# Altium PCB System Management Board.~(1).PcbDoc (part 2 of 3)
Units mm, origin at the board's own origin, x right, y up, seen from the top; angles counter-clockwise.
Board outline 150 x 110 mm, 4 copper layers (F.Cu, In1.Cu, In2.Cu, B.Cu); 151 components, 121 nets, 513 pads, 536 vias.
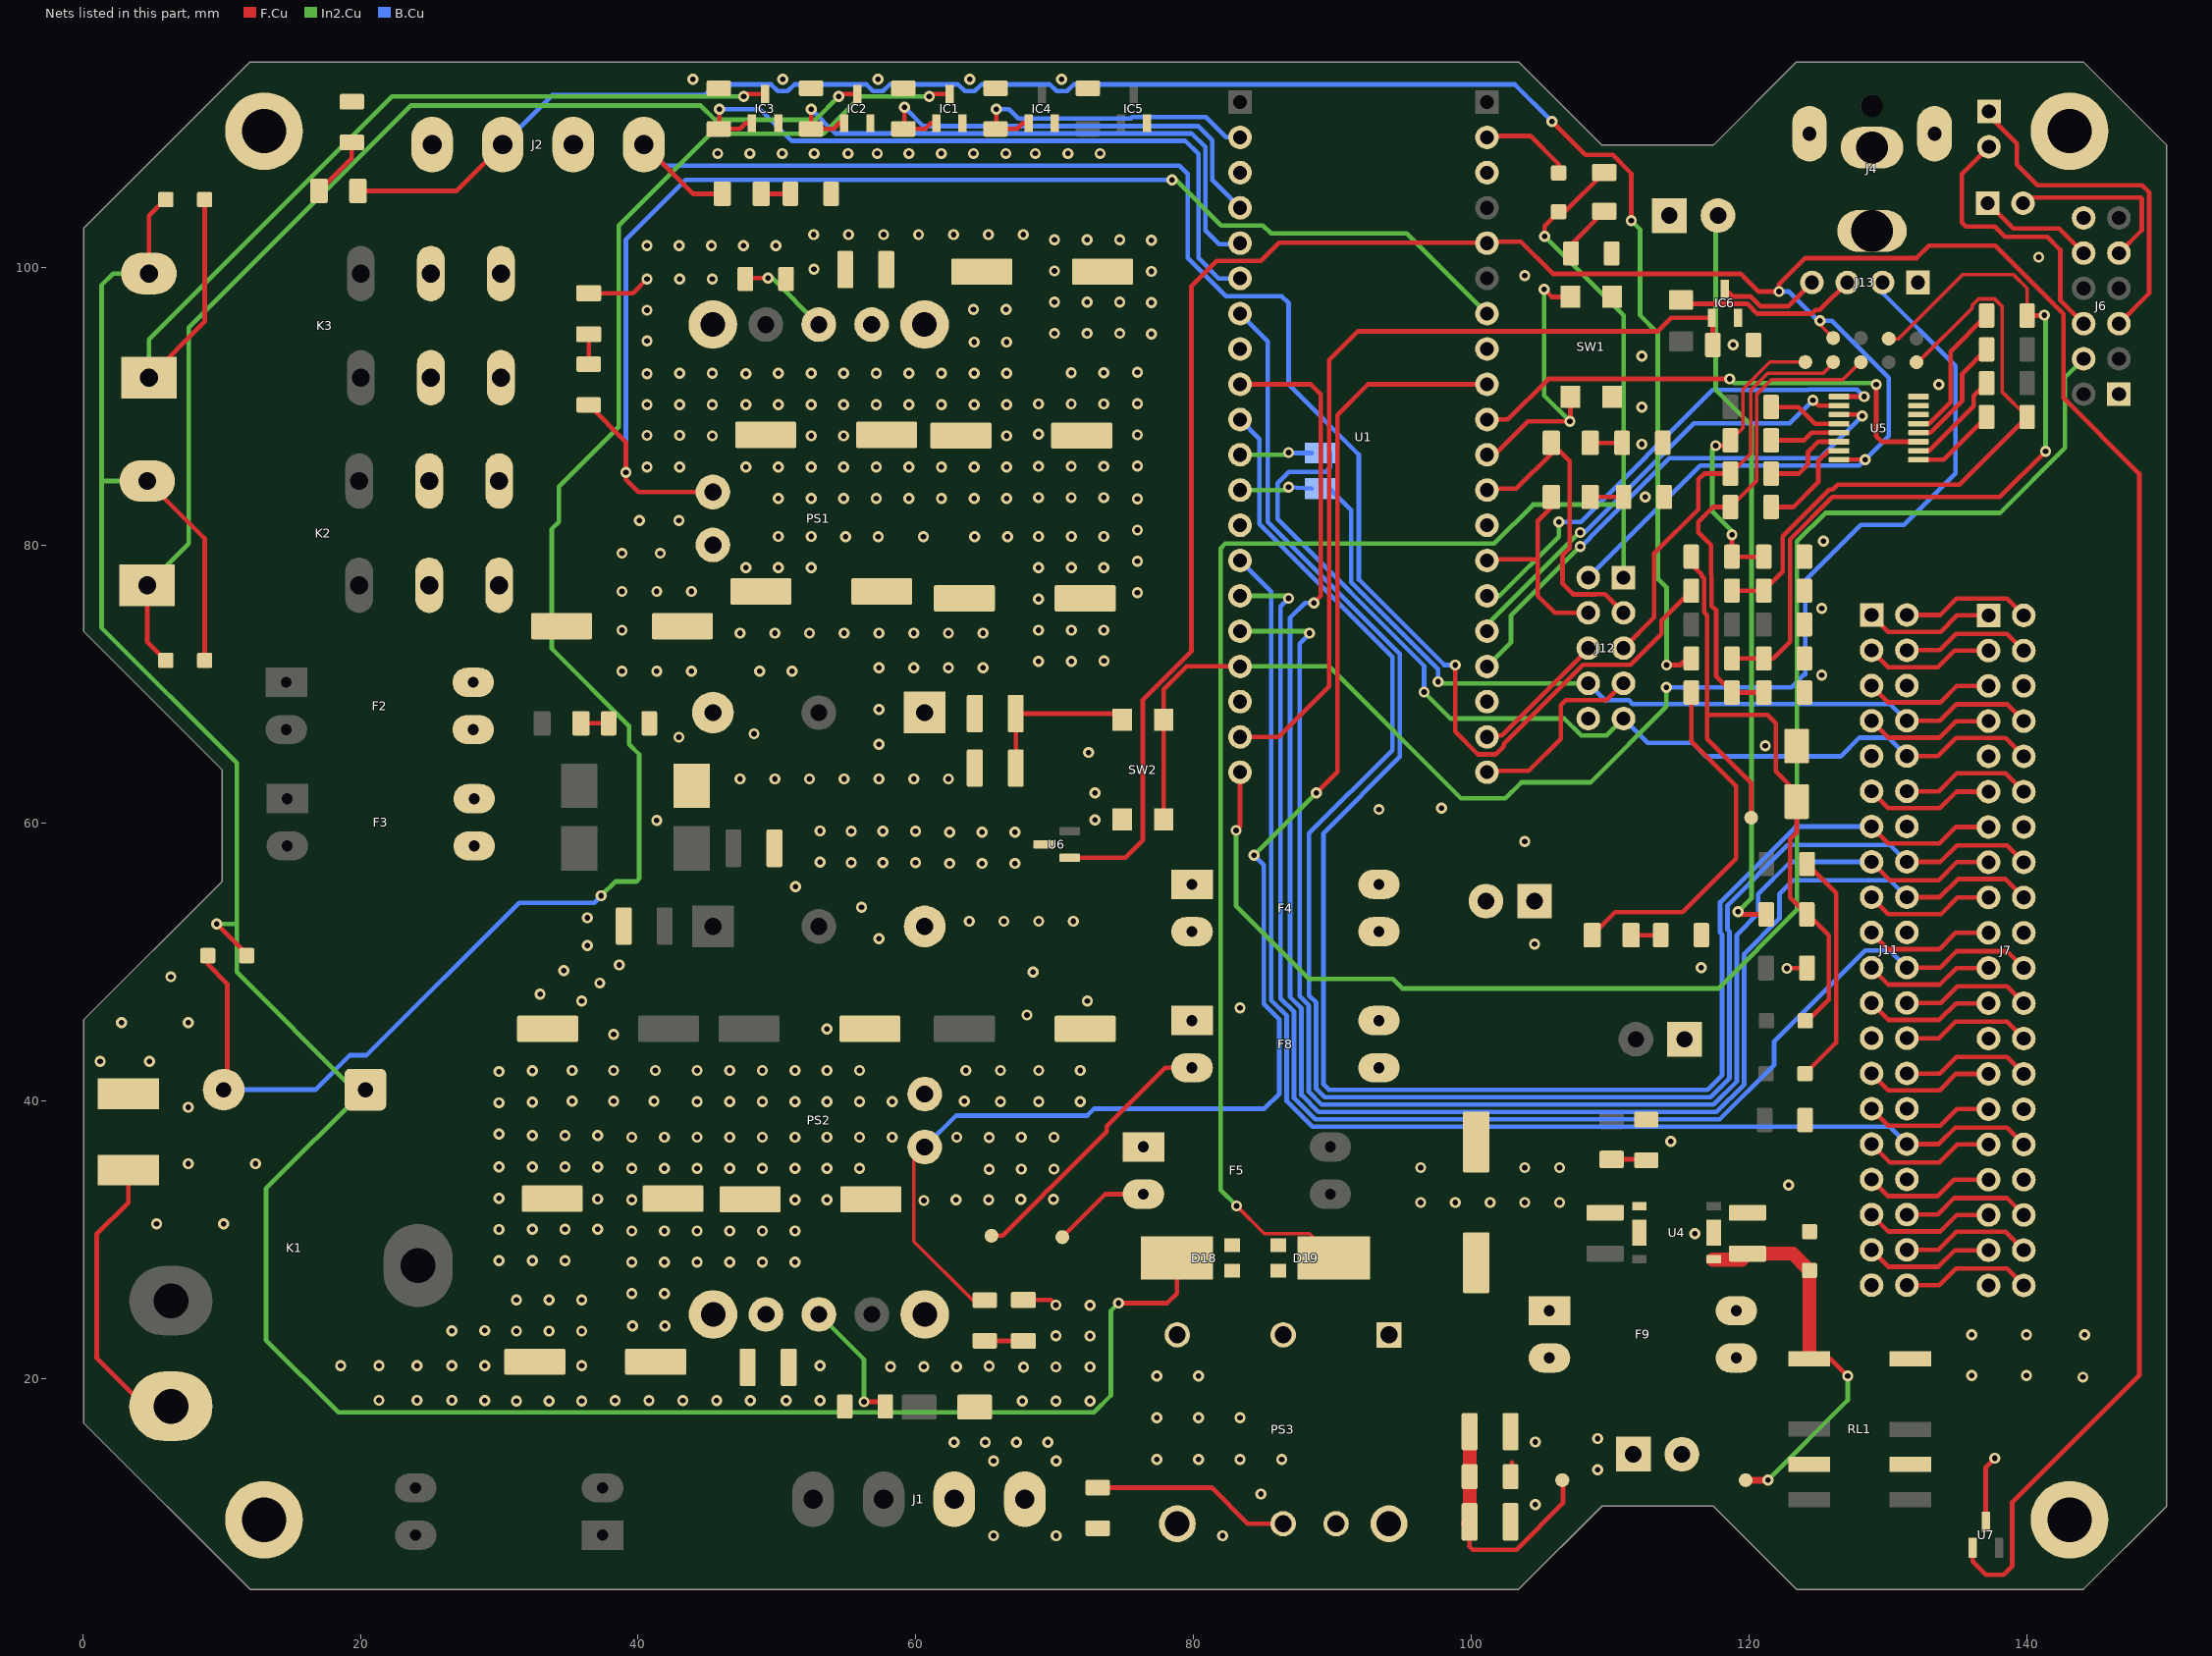
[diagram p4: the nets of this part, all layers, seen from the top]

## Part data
6 7 8 9 10 11 12 13 14 TP1 TP2 TP3 TP4 TP5: library part TestPoint
C1 C2 C3 C4 C9 C10 C11 C12 C15 C16 C22 C25 C26: library part C_Polarized, Voltage=63V
C5 C6 C7 C8 C13 C14 C17 C18 C19 C20 C21 C23 C24 C27: library part C, Voltage=63V
D1 D2: library part D_TVS
D3 D4 D5 D6 D7 D8 D9: library part D
D10 D11 D12 D13 D14 D15 D16 D17: library part LED
D18: library part SBRT15U50SP5-13_1
D19: library part SBRT15U50SP5-13
F1 F2 F3 F4 F5 F8 F9: library part 3557-10
F6 F7 F10: library part Fuse
H1 H2 H3 H4: library part MountingHole_Pad
IC1 IC2 IC3 IC4 IC5 IC6: library part SI2318CDS-T1-GE3, MANUFACTURER_NAME=Vishay
J1 J2: library part Conn_01x04_Male
J3 J8 J9 J10: library part Conn_01x02_Male
J4: library part PJ-063BH, Manufacturer="CUI INC"
J6: library part Conn_02x06_Counter_Clockwise
J7 J11: library part Conn_02x20_Odd_Even
J12: library part Conn_02x05_Top_Bottom
J13: library part Conn_01x04_Female
JP1 JP2: library part Jumper_2_Open
JP3 JP4: library part SolderJumper_2_Bridged
K1: library part RAYEX-L90S
K2 K3: library part J114FL1CS165VDC.41
PS1 PS2: library part I7C4W008A120V-0C3-R, Manufacturer=TDK, MAXIMUM_PACKAGE_HEIGHT="13.5 mm"
PS3: library part I3A4W008A033V-001-R, Manufacturer=TDK-Lambda, MAXIMUM_PACKAGE_HEIGHT=9.6mm
R1 R2 R3 R4 R5 R6 R7 R8 R9 R10 R11 R12 R13 R14 R15 R16 R17 R18 R19 R20 R21 R22 R23 R24 R25 R26 R27 R28 R29 R30 R31 R32 R33 R34 R35 R36 R37 R38 R39 R40 Rup1: library part R
RL1: library part EE2-5NU
SW1: library part SW_Push_4_PIN_1
SW2: library part SW_Push_4_PIN
U1: library part SC0915, Manufacturer="Raspberry Pi", MAXIMUM_PACKAGE_HEIGHT=3.73mm
U4: library part R1560S501B-E2-FE, "test"
U5: library part 74HC4051
U6 U7: library part MCP9700T-ETT

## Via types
v1: diameter 0.8, hole 0.4, F.Cu to B.Cu, tented both sides, 536 vias

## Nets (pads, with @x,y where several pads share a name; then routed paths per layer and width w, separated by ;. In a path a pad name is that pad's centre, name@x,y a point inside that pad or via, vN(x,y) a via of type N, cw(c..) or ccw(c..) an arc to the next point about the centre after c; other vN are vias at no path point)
"5V BOOTSTRAP": C21.1 D3.1 RL1.+ TP2.1 U4.1 | length 30.1
  F.Cu w0.33: D3.1@124.32,27.766 D3.1@124.34,27.787 D3.1@124.34,28.187 ; RL1.+@125.27,21.435 RL1.+@124.32,21.435 125.842,21.435 v1(127.09,20.187)
  F.Cu w0.5: TP2.1@119.74,12.687 v1(121.34,12.687)
  F.Cu w1: U4.1@117.377,28.567 119.448,28.567 C21.1@119.877,28.997 123.13,28.997 D3.1@124.34,27.787 124.34,21.455 RL1.+@124.32,21.435
  In2.Cu w0.33: v1(121.34,12.687) 127.09,18.437 v1(127.09,20.187)
"5V Intermediate": C23.1 C24.1 C27.1 D18.1 D18.2 D19.1 D19.2 PS3.7 PS3.8 TP3.1 | length 18.4
  F.Cu w0.33: C27.1@99.865,9.687 99.865,7.962 99.84,7.937 100.09,7.687 103.254,7.687 106.59,11.022 TP3.1@106.59,12.687 ; 99.94,13.912 99.965,13.937
  F.Cu w1: C27.1@99.727,9.549 C27.1@99.865,9.687 C23.1@99.865,12.937 C24.1@99.865,16.187
"5V Logic PWR": D9.2 D17.2 D19.3 J12.1 | length 125.5
  F.Cu w0.25: v1(83.09,32.437) 85.09,30.437 88.34,30.437 D19.3@90.09,28.687
  F.Cu w0.33: v1(105.258,102.249) 105.258,103.008 D9.2@106.274,104.024 106.722,104.024 D17.2@109.56,106.862
  In2.Cu w0.33: v1(83.09,32.437) 81.94,33.587 81.94,79.787 82.275,80.122 101.623,80.122 104.438,82.937 110.949,82.937 J12.1@110.949,77.686 110.949,96.558 v1(105.258,102.249)
"5V Relay PWR": D4.1 D5.1 D6.1 D18.3 K1.A1 K2.A2 K3.A2 | length 196.6
  F.Cu w0.33: K2.A2@4.655,84.637 8.79,80.501 D5.1@8.79,71.718 ; K3.A2@4.775,99.582 4.775,103.748 D6.1@5.931,104.903 ; v1(9.652,52.745) D4.1@11.814,50.583 ; v1(74.59,25.437) 78.09,25.437 78.786,26.132 D18.3@78.786,28.687
  In2.Cu w0.33: K2.A2@4.655,84.637 1.458,84.637 1.372,84.723 ; K3.A2@4.775,99.582 2.209,99.582 1.372,98.744 1.372,84.723 ; v1(9.652,52.745) 11.1,52.745 ; K1.A1@20.32,40.807 13.208,33.695 13.208,22.773 18.418,17.562 72.813,17.562 74.04,18.79 74.04,24.887 v1(74.59,25.437) ; K1.A1@20.36,41.021 19.344,41.021 11.1,49.265 11.1,52.745 ; 1.372,84.723 1.372,74.055 11.1,64.327 11.1,52.745
"15V Aux PWR OUT PROT": F8.3 F8.4 J9.2
"15v PWR": C9.1 C11.1 C15.1 C17.1 F4.1 F4.2 F8.1 F8.2 PS1.7 PS1.8 TP4.1 | length 19.7
  F.Cu w0.33: TP4.1@65.44,30.287 66.24,30.287 69.136,33.182 69.136,33.217 69.584,33.666 69.619,33.666 73.74,37.787 73.74,38.187 77.936,42.383 F8.2@79.878,42.383
  other v1: 54.79,83.387 57.14,83.387 59.49,83.387 61.84,83.387 64.19,83.387 66.54,83.387 54.79,85.637 57.14,85.637 59.49,85.637 61.84,85.637 64.19,85.637 66.54,85.637 54.79,87.887 66.54,87.887 54.79,90.137 57.14,90.137 59.49,90.137 61.84,90.137 64.19,90.137 66.54,90.137 54.79,92.387 57.14,92.387 59.49,92.387 61.84,92.387 64.19,92.387 66.54,92.387 64.19,94.637 66.54,94.637 64.14,96.987 66.49,96.987 57.675,102.387 60.191,102.387 62.707,102.387 65.224,102.387 67.74,102.387
"48V Aux PWR OUT PROT": F9.3 F9.4 J8.2
"48V PWR": C10.1 C12.1 C16.1 C18.1 F5.1 F5.2 F9.1 F9.2 PS2.7 PS2.8 TP5.1 | length 8.4
  F.Cu w0.33: TP5.1@70.54,30.187 73.636,33.283 F5.2@76.378,33.283 ; F9.1@105.209,25.288 F9.1@105.609,24.888
  F.Cu w1: F5.1@75.878,36.187 F5.1@76.378,36.687
  other v1: 38.34,18.419 40.777,18.419 43.215,18.419 45.652,18.419 48.089,18.419 39.59,23.787 41.94,23.787 39.54,26.137 41.89,26.137 39.54,28.387 41.89,28.387 44.24,28.387 46.59,28.387 48.94,28.387 51.29,28.387 39.54,30.637 41.89,30.637 44.24,30.637 46.59,30.637 48.94,30.637 51.29,30.637 39.54,32.887 51.29,32.887 39.54,35.137 41.89,35.137 44.24,35.137 46.59,35.137 48.94,35.137 51.29,35.137 39.54,37.387 41.89,37.387 44.24,37.387 46.59,37.387 48.94,37.387 51.29,37.387
"Analog Mux OUT": U1.31 U5.3 | length 36.3
  F.Cu w0.33: U1.31@101.12,89.067 102.616,89.067 105.537,91.988 v1(118.59,91.988) ; v1(129.14,91.587) 129.14,87.881 129.554,87.468 U5.3@132.191,87.468
  In2.Cu w0.33: v1(118.59,91.988) 118.891,91.687 129.04,91.687 v1(129.14,91.587)
Aux_ADC_IN: 7.1 J12.5 R14.1 | length 30.3
  F.Cu w0.25: R14.1@118.649,85.167 120.101,86.619 120.101,91.175 121.307,92.38 125.303,92.38 7.1@126.121,93.199
  F.Cu w0.33: J12.5@110.949,72.606 113.157,74.814 113.157,79.415 116.332,82.59 116.332,84.749 116.75,85.167 R14.1@118.649,85.167
Aux_SW: J13.2 SW2.1 U1.17 | length 101.4
  F.Cu w0.33: SW2.1@77.843,60.256 SW2.1@77.843,67.456 77.843,69.628 77.843,69.642 79.487,71.287 U1.17@83.34,71.287
  In2.Cu w0.33: U1.17@83.34,71.287 89.74,71.287 99.24,61.787 102.44,61.787 103.59,62.937 108.59,62.937 114.04,68.387 v1(114.04,69.787)
  B.Cu w0.33: v1(114.04,69.787) 123.04,69.787 123.94,70.687 124.04,70.687 124.04,77.487 128.04,81.487 131.14,81.487 134.84,85.187 134.84,92.937 129.6,98.177 J13.2@129.6,98.937
"Cap Discharge": K1.12 R40.1 | length 19.4
  F.Cu w0.33: R40.1@3.302,35.015 3.302,32.679 1.016,30.393 1.016,21.503 K1.12@4.512,18.007
"COMP PWR CM": PS1.34 R3.2 U1.34 | length 97.7
  F.Cu w0.33: R3.2@36.44,90.124 39.116,87.448 v1(39.116,85.257) 39.116,84.761 40.035,83.842 PS1.34@45.385,83.842
  In2.Cu w0.33: v1(78.44,106.317) 78.71,106.317 81.99,103.037 84.99,103.037 85.565,102.462 95.345,102.462 U1.34@101.12,96.687
  B.Cu w0.33: v1(39.116,85.257) 39.116,102.021 43.412,106.317 v1(78.44,106.317)
"COMP PWR EN": IC4.1 R9.1 U1.2 | length 22.4
  F.Cu w0.33: R9.1@65.736,109.994 67.283,109.994 67.695,110.407 IC4.1@68.107,110.407 ; R9.1@65.786,110.045 v1(65.786,111.419)
  B.Cu w0.33: v1(65.786,111.419) 66.708,111.419 67.39,110.737 75.49,110.737 75.59,110.837 80.89,110.837 82.34,109.387 U1.2@83.34,109.387
"COMP PWR OUT PROT": D13.2 F4.3 F4.4 J4.1 R27.2 | length 26.7
  F.Cu w0.33: D13.2@108.69,51.937 110.34,53.587 115.19,53.587 119.04,57.437 119.04,62.687 115.832,65.895 R27.2@115.832,69.148
  In2.Cu w0.33: J4.1@128.837,101.583 J4.1@128.837,102.644
  other v1: 103.84,58.687
"COMP_Vout MES_ADC": 8.1 R15.1 R27.1 R28.1 | length 35.7
  F.Cu w0.25: R15.1@118.649,82.767 120.551,84.669 120.551,90.892 121.59,91.93 126.734,91.93 8.1@128.028,93.224
  F.Cu w0.33: R15.1@118.649,82.767 117.398,82.767 116.332,81.701 116.332,80.939 117.243,80.028 117.243,77.888 117.289,77.842 117.289,75.651 117.624,75.316 117.624,70.543 R27.1@118.756,69.411 R28.1@121.044,69.411
CPS_IN_PROT: C1.1 C2.1 C3.1 C5.1 C7.1 F6.2 PS1.1
  other v1: 47.34,63.187 49.84,63.187 52.34,63.187 54.84,63.187 57.34,63.187 59.84,63.187 62.34,63.187 57.34,65.687 57.34,68.187 57.34,71.187 59.84,71.187 62.34,71.187 64.84,71.187 47.34,73.687 49.84,73.687 52.34,73.687 54.84,73.687 57.34,73.687 59.84,73.687 62.34,73.687 64.84,73.687
Ext_Relay_LOW_SIDE: IC6.3 J13.4 | length 7.5
  F.Cu w0.33: IC6.3@118.252,98.488 118.807,97.933 120.087,97.933 120.803,97.217 122.8,97.217 J13.4@124.52,98.937
Ext_Relay_Trig: IC6.1 R39.1 U1.19 | length 62.2
  F.Cu w0.33: U1.19@83.34,66.207 86.106,66.207 89.74,69.841 89.74,93.336 91.826,95.422 113.416,95.422 114.382,96.388 IC6.1@117.302,96.388 117.377,96.312 R39.1@117.378,94.437
GND: C1.2 C2.2 C3.2 C4.2 C5.2 C6.2 C7.2 C8.2 C9.2 C10.2 C11.2 C12.2 C13.2 C14.2 C15.2 C16.2 C17.2 C18.2 C19.2 C20.2 C21.2 C22.2 C23.2 C24.2 C25.2 C26.2 C27.2 D1.1 D2.1 D3.2 H1.1 H2.1 H3.1 H4.1 IC1.2 IC2.2 IC3.2 IC4.2 IC5.2 IC6.2 J1.1 J1.2 J2.2 J2.4 J3.1 J4.2 J4.S1 J4.S2 J6.1 J6.12 J7.6 J7.9 J7.14 J7.20 J7.25 J7.30 J7.34 J7.39 J8.1 J9.1 J10.1 J11.6 J11.9 J11.14 J11.20 J11.25 J11.30 J11.34 J11.39 J12.10 J13.1 PS1.3 PS1.4 PS1.32 PS2.3 PS2.4 PS2.32 PS3.2 PS3.3 PS3.4 R1.2 R2.2 R6.2 R7.2 R8.2 R9.2 R10.2 R12.1 R22.2 R24.2 R26.2 R28.2 R30.2 R31.2 R32.2 R33.2 R34.2 R35.2 R36.1 R37.1 R38.1 R39.2 R40.2 RL1.- Rup1.1 SW1.1 SW2.2 U1.3 U1.8 U1.13 U1.18 U1.23 U1.28 U1.33 U1.38 U4.2 U4.4 U4.5 U5.6 U5.7 U5.8 U6.3 U7.3 | length 25.3
  F.Cu w0.25: C14.2@67.727,25.649 C14.2@67.74,25.662
  F.Cu w0.33: C13.2@36.44,98.162 39.63,98.162 v1(40.64,99.172) ; C5.2@67.19,63.962 C7.2@67.19,67.887 74.412,67.887 SW2.2@74.843,67.456 ; C14.2@67.74,25.662 69.708,25.662 v1(70.079,25.291) ; C27.2@102.815,10.437 C27.2@102.915,10.537 ; 102.915,13.937 102.922,13.944 ; v1(122.707,49.544) 122.733,49.57 C19.2@124.157,49.57 ; U7.3@137.029,9.69 137.029,13.625 v1(137.668,14.264)
  other v1: 65.59,8.687 70.09,8.687 82.09,8.687 104.59,10.937 84.84,11.687 109.09,13.437 65.59,14.082 70.09,14.082 77.34,14.187 80.34,14.187 83.34,14.187 86.34,14.187 62.738,15.407 64.988,15.407 67.238,15.407 69.488,15.407 104.59,15.437 109.09,15.687 77.34,17.187 80.34,17.187 83.34,17.187 72.542,18.374 31.24,18.387 33.59,18.387 35.94,18.387 67.667,18.378 70.079,18.378 28.955,18.423 50.654,18.419 53.091,18.419 21.34,18.437 24.09,18.437 26.59,18.437 144.018,20.106 77.34,20.187 80.34,20.187 136.017,20.233 139.954,20.233 67.755,20.827 70.079,20.846 72.542,20.842 58.166,20.868 60.579,20.868 62.929,20.868 65.278,20.887 18.59,20.937 21.34,20.937 24.09,20.937 26.59,20.937 28.956,20.937 35.941,20.937 53.09,20.937 72.543,23.073 70.08,23.077 136.017,23.154 139.954,23.154 144.145,23.154 31.241,23.427 33.591,23.427 35.941,23.427 26.59,23.437 28.956,23.463 72.542,25.287 31.241,25.677 33.591,25.677 35.941,25.677 29.972,28.488 32.385,28.505 34.735,28.505 116.09,30.437 29.972,30.738 32.385,30.755 34.735,30.755 37.085,30.755 5.334,31.155 10.16,31.155 96.34,32.687 98.84,32.687 101.34,32.687 103.84,32.687 106.34,32.687 60.579,32.823 53.594,32.878 62.89,32.887 65.24,32.887 67.551,32.901 69.901,32.901 37.084,32.933 29.972,32.988 122.84,33.937 65.279,35.073 67.59,35.087 69.94,35.087 53.594,35.128 55.944,35.128 96.34,35.187 103.84,35.187 106.34,35.187 29.972,35.238 32.385,35.255 34.735,35.255 37.085,35.255 7.62,35.473 12.446,35.473 114.34,37.087 65.279,37.373 53.594,37.378 55.944,37.378 58.294,37.378 62.94,37.387 67.59,37.387 69.94,37.387 32.385,37.505 34.735,37.505 37.085,37.505 29.972,37.613 7.62,39.537 29.972,39.863 32.384,39.918 44.24,39.937 46.59,39.937 48.94,39.937 51.29,39.937 53.593,39.935 55.943,39.935 58.293,39.935 66.09,39.937 68.84,39.937 71.84,39.937 35.24,39.987 38.24,39.987 41.14,39.987 63.49,39.987 29.972,42.113 32.384,42.168 35.24,42.187 38.24,42.187 41.24,42.187 44.24,42.187 46.59,42.187 48.94,42.187 51.29,42.187 53.593,42.185 55.943,42.185 63.59,42.185 66.09,42.185 68.84,42.187 71.84,42.187 1.27,42.839 4.826,42.839 38.24,44.787 53.59,45.187 2.794,45.633 7.62,45.633 67.991,46.185 83.34,46.687 35.94,47.187 72.34,47.187 32.94,47.687 37.24,48.487 6.35,48.935 68.44,49.287 34.64,49.387 116.54,49.587 38.64,49.787 36.34,51.187 104.54,51.287 57.34,51.687 63.84,52.937 66.34,52.937 68.84,52.937 71.34,52.937 36.34,53.187 56.09,53.937 51.34,55.437 62.42,57.099 64.77,57.099 67.12,57.099 53.09,57.187 55.34,57.164 57.62,57.164 59.97,57.164 62.42,59.349 64.77,59.349 67.12,59.349 55.34,59.414 57.62,59.414 59.97,59.414 53.09,59.437 41.34,60.187 72.898,60.238 93.34,60.987 97.84,61.087 72.898,62.187 72.44,65.087 121.158,65.572 42.94,66.187 48.34,66.437 125.222,70.652 38.84,70.937 41.34,70.937 43.84,70.937 48.74,70.937 51.09,70.937 68.834,71.649 71.184,71.649 73.54,71.687 38.84,73.899 68.834,73.899 71.184,73.899 73.534,73.899 125.222,75.478 68.834,76.149 75.946,76.602 38.84,76.687 41.34,76.687 43.84,76.687 47.751,78.399 50.101,78.399 52.451,78.399 68.834,78.399 71.184,78.399 73.534,78.399 75.946,78.852 38.84,79.437 41.59,79.437 125.349,80.304 50.101,80.649 52.451,80.649 54.94,80.637 57.29,80.637 60.54,80.637 64.24,80.637 66.59,80.637 68.834,80.649 71.184,80.649 73.534,80.649 75.946,81.102 40.09,81.787 42.94,81.787 75.946,83.352 50.101,83.388 52.451,83.388 68.833,83.443 71.183,83.443 73.533,83.443 112.522,83.479 40.639,85.638 42.989,85.638 47.751,85.638 50.101,85.638 52.451,85.638 68.833,85.693 71.183,85.693 73.533,85.693 75.946,85.71 112.268,87.289 45.339,87.888 52.451,87.888 40.64,87.924 42.99,87.924 75.946,87.96 68.834,88.015 112.268,89.956 40.639,90.138 42.989,90.138 45.339,90.138 47.751,90.138 50.101,90.138 52.451,90.138 68.833,90.193 71.183,90.193 73.533,90.193 75.946,90.21 133.64,91.587 40.64,92.369 42.989,92.388 45.339,92.388 47.752,92.369 50.101,92.388 52.451,92.388 71.183,92.443 73.533,92.443 75.946,92.46 112.268,93.639 118.84,94.437 40.64,94.727 76.962,95.235 69.977,95.271 72.327,95.271 74.677,95.271 40.639,96.941 76.962,97.485 69.977,97.521 72.327,97.521 74.677,97.521 42.989,99.191 45.339,99.191 103.84,99.437 76.962,99.735 69.977,99.771 52.654,99.887 140.843,100.751 40.64,101.585 42.958,101.585 45.276,101.585 47.593,101.585 49.911,101.585 76.962,101.985 69.977,102.021 72.327,102.021 74.677,102.021 52.642,102.387 55.158,102.387 45.733,108.219 48.05,108.219 50.368,108.219 52.683,108.219 55.105,108.219 57.213,108.219 59.497,108.219 61.822,108.219 64.149,108.219 66.478,108.219 68.602,108.219 70.948,108.219 73.264,108.219 43.942,113.578 50.419,113.578 57.277,113.578 63.881,113.578 70.485,113.578
i3_Vin: C22.1 PS3.1 RL1.C1 RL1.C2 | length 1
  F.Cu w0.33: RL1.C1@124.32,13.815 RL1.C1@124.324,13.81
  F.Cu w1: RL1.C1@123.37,13.815 RL1.C1@124.32,13.815 ; RL1.C2@131.592,13.815 RL1.C2@131.597,13.81
JET_ON: J6.4 U1.20 | length 110.5
  F.Cu w0.33: v1(83.058,59.476) 83.34,59.758 U1.20@83.34,63.667
  In2.Cu w0.33: v1(83.058,59.476) 83.058,54.015 88.286,48.787 94.34,48.787 95.04,48.087 117.77,48.087 123.444,53.761 123.444,80.304 125.476,82.336 138.049,82.336 142.74,87.027 142.74,92.095 J6.4@144.076,93.431
JET_P1: J7.1 J11.1 | length 9.4
  F.Cu w0.33: J11.1@128.808,74.991 130.023,73.775 133.779,73.775 134.968,74.965 J7.1@137.227,74.965
JET_P2: J7.2 J11.2 | length 9.4
  F.Cu w0.33: J11.2@131.348,74.991 133.744,74.991 134.933,76.18 138.552,76.18 J7.2@139.767,74.965
JET_P3: J7.3 J11.3 | length 9.4
  F.Cu w0.33: J11.3@128.808,72.451 130.023,71.235 133.589,71.235 134.778,72.425 J7.3@137.227,72.425
JET_P4: J7.4 J11.4 | length 9.4
  F.Cu w0.33: J11.4@131.348,72.451 133.704,72.451 134.893,73.64 138.552,73.64 J7.4@139.767,72.425
JET_P5: J7.5 J11.5 | length 9.4
  F.Cu w0.33: J11.5@128.808,69.911 130.023,68.695 133.749,68.695 134.938,69.885 J7.5@137.227,69.885
JET_P7: J7.7 J11.7 | length 9.4
  F.Cu w0.33: J11.7@128.808,67.371 130.023,66.155 133.709,66.155 134.898,67.345 J7.7@137.227,67.345
JET_P11: J7.11 J11.11 | length 9.4
  F.Cu w0.33: J11.11@128.808,62.291 130.023,61.075 133.729,61.075 134.918,62.265 J7.11@137.227,62.265
JET_P12: J7.12 J11.12 | length 9.5
  F.Cu w0.33: J11.12@131.348,62.291 133.644,62.291 134.94,63.587 138.445,63.587 J7.12@139.767,62.265
JET_P17: J7.17 J11.17 | length 9.4
  F.Cu w0.33: J11.17@128.808,54.671 130.023,53.455 133.809,53.455 134.998,54.645 J7.17@137.227,54.645
JET_P19: J7.19 J11.19 | length 9.4
  F.Cu w0.33: J11.19@128.808,52.131 130.023,50.915 133.669,50.915 134.858,52.105 J7.19@137.227,52.105
JET_P21: J7.21 J11.21 | length 9.4
  F.Cu w0.33: J11.21@128.808,49.591 130.023,48.375 133.729,48.375 134.918,49.565 J7.21@137.227,49.565
JET_P23: J7.23 J11.23 | length 9.4
  F.Cu w0.33: J11.23@128.808,47.051 130.023,45.835 133.689,45.835 134.878,47.025 J7.23@137.227,47.025
JET_P24: J7.24 J11.24 | length 9.4
  F.Cu w0.33: J11.24@131.348,47.051 133.804,47.051 134.993,48.24 138.552,48.24 J7.24@139.767,47.025
JET_P26: J7.26 J11.26 | length 9.4
  F.Cu w0.33: J11.26@131.348,44.511 133.664,44.511 134.853,45.7 138.552,45.7 J7.26@139.767,44.485
JET_P27: J7.27 J11.27 | length 9.4
  F.Cu w0.33: J11.27@128.808,41.971 130.023,40.755 133.709,40.755 134.898,41.945 J7.27@137.227,41.945
JET_P28: J7.28 J11.28 | length 9.4
  F.Cu w0.33: J11.28@131.348,41.971 133.724,41.971 134.913,43.16 138.552,43.16 J7.28@139.767,41.945
JET_P29: J7.29 J11.29 | length 9.4
  F.Cu w0.33: J11.29@128.808,39.431 130.023,38.215 133.769,38.215 134.958,39.405 J7.29@137.227,39.405
JET_P31: J7.31 J11.31 | length 9.5
  F.Cu w0.33: J11.31@128.808,36.891 130.133,35.566 133.697,35.566 134.996,36.865 J7.31@137.227,36.865
JET_P33: J7.33 J11.33 | length 9.4
  F.Cu w0.33: J11.33@128.808,34.351 130.023,33.135 133.551,33.135 134.74,34.325 J7.33@137.227,34.325
JET_P35: J7.35 J11.35 | length 9.4
  F.Cu w0.33: J11.35@128.808,31.811 130.023,30.595 133.749,30.595 134.938,31.785 J7.35@137.227,31.785
JET_P36: J7.36 J11.36 | length 9.4
  F.Cu w0.33: J11.36@131.348,31.811 133.564,31.811 134.753,33 138.552,33 J7.36@139.767,31.785
JET_P37: J7.37 J11.37 | length 9.4
  F.Cu w0.33: J11.37@128.808,29.271 130.023,28.055 133.609,28.055 134.798,29.245 J7.37@137.227,29.245
JET_P38: J7.38 J11.38 | length 9.5
  F.Cu w0.33: J11.38@131.348,29.271 133.624,29.271 134.923,30.57 138.442,30.57 J7.38@139.767,29.245
JET_P40: J7.40 J11.40 | length 9.4
  F.Cu w0.33: J11.40@131.348,26.731 133.684,26.731 134.873,27.92 138.552,27.92 J7.40@139.767,26.705
Jet_UART1_Rx: J7.10 J11.10 J12.9 JP3.1 | length 73
  F.Cu w0.33: J11.10@131.348,64.831 133.584,64.831 134.883,66.13 138.442,66.13 J7.10@139.767,64.805
  In2.Cu w0.33: v1(96.59,69.437) 98.495,67.531 106.685,67.531 107.906,66.31 109.734,66.31 J12.9@110.949,67.526
  B.Cu w0.33: JP3.1@89.8,86.654 89.8,85.573 89.513,85.287 86.858,85.287 86.04,84.469 86.04,81.887 96.59,71.337 v1(96.59,69.437) ; J12.9@110.949,67.526 112.688,65.787 115.924,65.787 116.904,64.806 126.591,64.806 127.94,66.155 130.023,66.155 J11.10@131.348,64.831
Jet_UART1_Tx: J7.8 J11.8 J12.8 JP4.1 | length 61.5
  F.Cu w0.33: J11.8@131.348,67.371 133.724,67.371 134.913,68.56 138.552,68.56 J7.8@139.767,67.345
  In2.Cu w0.33: v1(97.59,70.187) 97.711,70.066 J12.8@108.409,70.066
  B.Cu w0.33: JP4.1@89.8,84.09 91.34,82.55 91.34,77.336 97.59,71.086 v1(97.59,70.187) ; J12.8@108.409,70.066 109.624,68.85 111.343,68.85 111.607,68.586 130.133,68.586 J11.8@131.348,67.371
"KeySW_Vin MES_ADC": 6.1 R13.1 R21.1 R22.1 | length 21.6
  F.Cu w0.25: R13.1@118.649,87.567 119.536,88.454 119.536,91.246 121.495,93.205 6.1@124.04,93.205
  F.Cu w0.33: v1(117.59,87.187) 118.269,87.187 R13.1@118.649,87.567 ; v1(118.757,80.77) R21.1@118.756,79.187 R22.1@121.044,79.187
  In2.Cu w0.33: v1(117.59,87.187) 117.34,86.937 117.34,82.437 118.757,81.02 v1(118.757,80.77)
"KeySwitch IN": D2.2 D7.2 R5.2 R21.2 TP1.1 | length 50.2
  F.Cu w0.33: R21.2@115.832,79.187 115.832,78.645 116.586,77.891 116.586,77.795 116.759,77.623 116.759,75.178 116.967,74.97 116.967,68.239 ; TP1.1@120.14,60.387 120.14,62.887 116.967,66.06 116.967,68.239 ; R5.2@124.144,53.43 122.936,54.639 122.936,58.841 123.416,59.321 D2.2@123.416,61.554 123.416,62.232 121.923,63.724 121.923,67.185 121.322,67.787 116.967,67.787 116.967,68.239 ; D7.2@124.216,45.77 125.73,47.284 125.73,51.932 R5.2@124.231,53.43
"Light A Relay EN": IC2.1 R7.1 U1.5 | length 42.4
  F.Cu w0.33: R7.1@52.45,109.994 54.075,109.994 54.487,110.407 IC2.1@54.822,110.407 ; R7.1@52.45,109.994 v1(52.451,111.419)
  B.Cu w0.33: v1(52.451,111.419) 54.207,109.662 78.083,109.662 79.864,109.662 80.84,108.687 80.84,102.687 81.84,101.687 82.68,101.687 82.76,101.767 U1.5@83.34,101.767
"Light B Relay EN": IC3.1 R8.1 U1.6 | length 50.9
  F.Cu w0.33: R8.1@45.808,109.994 47.344,109.994 47.756,110.407 IC3.1@48.179,110.407 ; R8.1@45.847,110.034 v1(45.847,111.419)
  B.Cu w0.33: v1(45.847,111.419) 48.768,111.419 51.054,109.133 79.394,109.133 80.34,108.187 80.34,100.687 81.8,99.227 U1.6@83.34,99.227
"LIGHT BANK A PROT": F2.3 F2.4 K2.11
"LIGHT BANK A PROT SW": D11.2 J2.1 K2.14 R25.2 | length 121.3
  F.Cu w0.33: J2.1@40.41,108.862 43.951,105.321 D11.2@46.06,105.321 ; v1(98.84,71.387) 98.84,66.587 100.479,64.947 101.74,64.947 102.335,65.542 102.335,65.71 108.015,71.39 111.452,71.39 113.687,73.625 113.687,74.598 R25.2@115.832,76.743
  B.Cu w0.33: J2.1@40.41,108.862 41.917,107.355 78.972,107.355 79.575,106.752 79.575,100.702 82.326,97.95 86.335,97.95 86.84,97.445 86.84,91.594 91.89,86.544 91.89,77.536 98.04,71.387 v1(98.84,71.387)
"LIGHT BANK B PROT": F3.3 F3.4 K3.11
"LIGHT BANK B PROT SW": D12.2 J2.3 K3.14 R29.2 | length 137.2
  F.Cu w0.33: D12.2@19.827,105.522 26.91,105.522 J2.3@30.25,108.862 ; v1(105.791,110.53) 108.204,108.117 110.182,108.117 111.506,106.792 v1(111.506,103.387) ; v1(114.046,71.387) 115.035,71.387 R29.2@115.503,71.855
  In2.Cu w0.33: v1(111.506,103.387) 112.141,102.752 112.141,96.56 113.411,95.29 113.411,77.631 114.046,76.996 v1(114.046,71.387)
  B.Cu w0.33: J2.3@30.25,108.862 33.823,112.435 44.831,112.435 45.593,113.197 49.577,113.197 50.061,112.713 50.777,112.713 51.261,113.197 56.435,113.197 56.919,112.713 57.635,112.713 58.119,113.197 63.039,113.197 63.523,112.713 64.239,112.713 64.723,113.197 69.643,113.197 70.127,112.713 70.89,112.713 71.374,113.197 103.124,113.197 v1(105.791,110.53)
"Light_A_Vout MES_ADC": 10.1 R17.1 R25.1 R26.1 | length 45
  F.Cu w0.25: 10.1@132.04,93.187 132.143,93.187 136.04,97.083 136.04,97.287 136.505,97.752 137.659,97.752 138.224,97.187 138.224,91.039 R17.1@140.011,89.252
  F.Cu w0.33: R25.1@118.756,76.743 R26.1@121.044,76.743 122.406,78.105 122.406,80.65 125.765,84.008 126.019,84.008 126.378,84.368 135.127,84.368 R17.1@140.011,89.252
"Light_B_Vout MES_ADC": 12.1 R18.1 R29.1 R30.1 | length 58.4
  F.Cu w0.25: 12.1@130.04,94.887 130.74,94.887 135.34,99.487 139.04,99.487 140.012,98.515 R18.1@140.011,96.552
  F.Cu w0.33: R29.1@118.756,71.855 R30.1@121.044,71.855 121.726,71.855 122.936,73.065 122.936,80.431 125.984,83.479 138.032,83.479 v1(141.34,86.787) ; R18.1@140.011,96.552 141.205,96.552 v1(141.24,96.587)
  In2.Cu w0.33: v1(141.24,96.587) 141.34,96.487 v1(141.34,86.787)
"Main Relay EN": IC1.1 R6.1 U1.4 | length 32.8
  F.Cu w0.33: R6.1@59.093,109.994 60.679,109.994 61.091,110.407 IC1.1@61.464,110.407 ; R6.1@59.182,110.084 v1(59.182,111.546)
  B.Cu w0.33: v1(59.182,111.546) 60.536,110.192 78.303,110.192 78.308,110.187 80.34,110.187 81.34,109.187 81.34,106.307 U1.4@83.34,104.307
MUX_S0: U1.24 U5.11 | length 37.4
  F.Cu w0.33: U5.11@126.466,89.418 128.046,89.418 v1(128.143,89.321)
  In2.Cu w0.33: U1.24@101.12,71.287 102.84,73.007 102.84,74.936 v1(107.826,79.922)
  B.Cu w0.33: v1(107.826,79.922) 107.908,79.922 108.591,80.605 108.591,80.63 114.248,86.287 125.109,86.287 v1(128.143,89.321)
MUX_S1: U1.25 U5.10 | length 32.7
  F.Cu w0.33: v1(124.587,90.464) 124.983,90.068 U5.10@126.466,90.068
  In2.Cu w0.33: U1.25@101.12,73.827 101.12,74.298 107.744,80.922 v1(107.826,80.922)
  B.Cu w0.33: v1(107.826,80.922) 108.134,80.922 115.998,88.787 122.91,88.787 v1(124.587,90.464)
MUX_S2: U1.26 U5.9 | length 35.9
  F.Cu w0.33: U5.9@126.466,90.718 v1(128.27,90.718)
  In2.Cu w0.33: U1.26@101.12,76.367 102.02,76.367 106.296,80.642 v1(106.296,81.687)
  B.Cu w0.33: v1(106.296,81.687) 107.87,81.687 117.37,91.187 124.228,91.187 124.27,91.229 127.759,91.229 v1(128.27,90.718)
NetC13_1: C13.1 R3.1 | length 2.2
  F.Cu w0.33: R3.1@36.44,93.049 C13.1@36.44,95.212
NetC14_1: C14.1 R4.1 | length 2.8
  F.Cu w0.33: R4.1@64.96,22.724 64.972,22.712 C14.1@67.74,22.712
NetD4_2: D4.2 IC1.3 K1.A2 | length 125.6
  F.Cu w0.33: D4.2@9.014,50.459 9.014,49.827 10.414,48.427 K1.A2@10.414,41.061 ; v1(60.96,112.332) 61.135,112.507 IC1.3@62.414,112.507
  In2.Cu w0.33: v1(37.338,54.777) 38.354,55.793 39.878,55.793 40.075,55.989 40.075,64.952 39.34,65.687 39.34,66.999 33.782,72.557 33.782,81.193 34.29,81.701 34.29,84.241 38.608,88.559 38.608,103.037 45.212,109.641 53.34,109.641 56.031,112.332 v1(60.96,112.332)
  B.Cu w0.33: K1.A2@10.16,40.807 16.76,40.807 19.24,43.287 20.44,43.287 31.422,54.269 36.83,54.269 v1(37.338,54.777)
NetD5_2: D5.2 IC2.3 K2.A1 | length 81.7
  F.Cu w0.33: K2.A1@4.655,77.137 4.655,73.054 D5.2@5.99,71.718 ; v1(54.451,112.332) 54.626,112.507 IC2.3@55.772,112.507
  In2.Cu w0.33: K2.A1@4.655,77.137 7.645,80.127 7.645,95.696 23.622,111.673 44.511,111.673 45.53,110.653 52.773,110.653 v1(54.451,112.332)
NetD6_2: D6.2 IC3.3 K3.A1 | length 68.9
  F.Cu w0.33: K3.A1@4.775,92.082 8.79,96.097 D6.2@8.79,104.903 ; v1(47.598,112.332) 47.773,112.507 IC3.3@49.129,112.507
  In2.Cu w0.33: K3.A1@4.775,92.082 4.775,94.832 22.275,112.332 v1(47.598,112.332)
NetD8_2: D8.2 R11.2 | length 16.9
  F.Cu w0.33: D8.2@124.017,41.96 126.26,44.203 126.26,54.957 R11.2@124.166,57.051
NetD9_1: D9.1 U1.39 | length 6
  F.Cu w0.33: U1.39@101.76,109.492 104.238,109.492 106.274,107.456 D9.1@106.274,106.824
NetD10_1: D10.1 R31.1 | length 2.3
  F.Cu w0.33: D10.1@35.884,67.411 D10.1@35.884,67.187 ; D10.1@35.95,67.253 D10.1@35.884,67.187 ; R31.1@37.878,67.187 D10.1@35.884,67.187
NetD11_1: D11.1 R32.1 | length 2.1
  F.Cu w0.33: D11.1@48.86,105.321 R32.1@50.969,105.321
NetD12_1: D12.1 R33.1 | length 4.5
  F.Cu w0.33: D12.1@17.027,105.522 19.391,107.886 R33.1@19.391,109.022
NetD13_1: D13.1 R34.1 | length 2.1
  F.Cu w0.33: D13.1@111.49,51.937 R34.1@113.628,51.937
NetD14_1: D14.1 R35.1 | length 2.5
  F.Cu w0.33: D14.1@110.09,35.787 112.527,35.787 R35.1@112.59,35.724
NetD15_1: D15.1 R36.2 | length 2.3
  F.Cu w0.33: D15.1@108.55,87.388 R36.2@110.847,87.388
NetD16_1: D16.1 R37.2 | length 2.4
  F.Cu w0.33: D16.1@108.55,83.488 R37.2@110.956,83.488
NetD17_1: D17.1 R38.2 | length 3.4
  F.Cu w0.33: R38.2@107.167,101.669 D17.1@109.56,104.062
NetF10_2: F10.2 J13.3 | length 13.3
  F.Cu w0.33: F10.2@115.09,97.674 115.361,97.403 119.867,97.403 120.583,96.687 124.508,96.687 124.773,96.952 125.075,96.952 J13.3@127.06,98.937
NetJ6_5: J6.5 JP1.1 | length 25.1
  F.Cu w0.33: JP1.1@137.259,110.939 139.268,108.929 139.268,107.431 140.767,105.932 148.285,105.932 148.793,105.424 148.793,98.148 J6.5@146.616,95.971
NetJ6_6: J6.6 JP1.2 | length 20.2
  F.Cu w0.33: JP1.2@137.259,108.704 135.306,106.751 135.306,103.24 135.585,102.96 137.693,102.96 138.421,102.233 139.056,102.233 139.065,102.224 141.453,102.224 142.392,101.284 142.392,97.652 142.494,97.55 142.496,97.55 J6.6@144.076,95.971
NetJ6_9: J6.9 JP2.2 | length 12.8
  F.Cu w0.33: JP2.2@140.112,105.043 148.209,105.043 148.263,104.989 148.263,102.698 J6.9@146.616,101.051
NetJ6_10: J6.10 JP2.1 | length 8.4
  F.Cu w0.33: JP2.1@137.208,104.64 139.014,102.833 142.293,102.833 J6.10@144.076,101.051
NetJ10_2: J10.2 R5.1 | length 53.8
  F.Cu w0.33: v1(119.202,53.634) 119.405,53.43 R5.1@121.22,53.43
  In2.Cu w0.33: J10.2@117.748,103.751 117.59,103.593 117.59,91.187 120.167,88.609 120.167,54.599 v1(119.202,53.634)
NetJP3_2: JP3.2 U1.11 | length 5.2
  In2.Cu w0.33: U1.11@83.34,86.527 86.68,86.527 v1(86.84,86.687)
  B.Cu w0.33: v1(86.84,86.687) 86.873,86.654 JP3.2@88.5,86.654
NetJP4_2: JP4.2 U1.12 | length 5.2
  In2.Cu w0.33: U1.12@83.34,83.987 86.64,83.987 v1(86.84,84.187)
  B.Cu w0.33: v1(86.84,84.187) JP4.2@88.5,84.09
NetPS1_6: PS1.6 R1.1 | length 6.6
  F.Cu w0.33: R1.1@47.793,99.252 v1(49.352,99.252)
  In2.Cu w0.33: v1(49.352,99.252) 49.655,99.252 PS1.6@53.005,95.902
NetPS2_6: PS2.6 R2.1 | length 8.8
  F.Cu w0.33: v1(56.261,18.328) R2.1@57.466,18.328
  In2.Cu w0.33: PS2.6@53.015,24.622 56.261,21.376 v1(56.261,18.328)
NetPS3_6: PS3.6 Rup1.2 | length 14.4
  F.Cu w0.33: Rup1.2@73.09,12.149 81.295,12.149 83.895,9.549 PS3.6@86.44,9.549
NetR13_2: R13.2 U5.13 | length 5.1
  F.Cu w0.33: R13.2@121.574,87.567 123.925,87.567 124.485,88.127 U5.13@126.457,88.127
NetR14_2: R14.2 U5.14 | length 6.4
  F.Cu w0.33: R14.2@121.574,85.167 123.557,85.167 124.231,85.841 124.231,86.73 124.969,87.468 U5.14@126.466,87.468
NetR15_2: R15.2 U5.15 | length 7.5
  F.Cu w0.33: R15.2@121.574,82.767 123.189,82.767 124.968,84.545 124.968,86.065 125.721,86.818 U5.15@126.466,86.818
NetR16_2: R16.2 U5.12 | length 5.4
  F.Cu w0.33: R16.2@121.574,89.967 123.535,89.967 124.734,88.768 U5.12@126.466,88.768
NetR17_2: R17.2 U5.1 | length 6.2
  F.Cu w0.33: U5.1@132.191,86.168 134.003,86.168 R17.2@137.087,89.252
NetR18_2: R18.2 U5.5 | length 10.2
  F.Cu w0.33: U5.5@132.191,88.768 132.936,88.768 134.493,90.324 134.493,93.958 R18.2@137.087,96.552
NetR19_2: R19.2 U5.2 | length 7.3
  F.Cu w0.33: U5.2@132.191,86.818 132.936,86.818 136.159,90.041 136.159,90.757 R19.2@137.087,91.685
NetR20_2: R20.2 U5.4 | length 8.5
  F.Cu w0.33: U5.4@132.191,88.118 133.035,88.118 135.331,90.413 135.331,92.363 R20.2@137.087,94.118
NetSW1_2: SW1.2 U1.30 | length 20.4
  F.Cu w0.33: U1.30@101.76,86.632 104.065,88.937 v1(107.09,88.937) 107.119,88.966 SW1.2@107.119,90.698 ; v1(105.24,98.437) 105.779,97.898 SW1.2@107.119,97.898
  In2.Cu w0.33: v1(105.24,98.437) 105.24,90.787 v1(107.09,88.937)
"PICO 3V3": 14.1 J12.2 U1.36 U5.16 U6.1 U7.1 | length 260.5
  F.Cu w0.25: v1(125.09,96.187) 125.09,95.887 14.1@126.04,94.937
  F.Cu w0.33: U6.1@71.069,57.518 75.071,57.518 76.34,58.787 76.34,68.887 77.313,69.859 77.313,69.862 79.84,72.389 79.84,98.687 81.653,100.499 84.853,100.499 86.14,101.787 101.1,101.787 U1.36@101.12,101.767 ; U1.36@101.76,101.872 103.552,101.872 105.867,99.557 119.37,99.557 120.64,98.287 v1(122.14,98.287) 122.14,98.787 124.04,100.687 132.04,100.687 132.94,101.587 137.721,101.587 141.862,97.445 141.862,97.432 142.274,97.02 142.277,97.02 142.621,96.676 142.621,90.627 148.082,85.166 148.082,20.233 138.938,11.089 138.938,6.517 138.303,5.882 137.033,5.882 136.079,6.836 U7.1@136.079,7.815 ; U5.16@126.466,86.168 126.485,86.187 v1(128.34,86.187)
  B.Cu w0.33: J12.2@108.409,77.686 116.48,85.756 127.91,85.756 v1(128.34,86.187) 130.04,87.887 130.04,92.087 125.94,96.187 v1(125.09,96.187) 124.94,96.187 122.84,98.287 v1(122.14,98.287)
"PICO IN BIT 0": J7.16 J11.16 U1.10 | length 123.2
  F.Cu w0.33: J11.16@131.348,57.211 133.764,57.211 134.953,58.4 138.552,58.4 J7.16@139.767,57.185
  B.Cu w0.33: U1.10@83.34,89.067 84.74,87.667 84.74,81.543 94.31,71.973 94.31,65.266 88.31,59.266 88.31,47.595 88.817,47.088 88.817,40.865 89.422,40.26 117.207,40.26 118.58,41.633 118.58,52.186 118.437,52.328 118.437,54.088 122.775,58.426 130.133,58.426 J11.16@131.348,57.211
"PICO IN BIT 1": J7.32 J11.32 U1.14 | length 95.7
  F.Cu w0.33: J11.32@131.348,36.891 133.644,36.891 134.833,38.08 138.552,38.08 J7.32@139.767,36.865
  B.Cu w0.33: U1.14@83.34,78.907 85.583,76.664 85.583,47.244 86.697,46.13 86.697,39.986 88.543,38.14 130.099,38.14 J11.32@131.348,36.891
"PICO IN BIT 2": J7.22 J11.22 U1.15 | length 100.9
  F.Cu w0.33: J11.22@131.348,49.591 133.739,49.591 134.928,50.78 138.552,50.78 J7.22@139.767,49.565
  In2.Cu w0.33: U1.15@83.34,76.367 86.66,76.367 v1(86.84,76.187)
  B.Cu w0.33: v1(86.84,76.187) 86.262,75.609 86.262,47.364 87.227,46.4 87.227,40.206 88.763,38.67 117.866,38.67 121.793,42.597 121.793,44.294 128.339,50.84 130.099,50.84 J11.22@131.348,49.591
"Pico LED A": D15.2 J12.3 U1.29 | length 22
  F.Cu w0.33: U1.29@101.76,84.092 103.229,84.092 105.75,86.613 D15.2@105.75,87.388 107.061,86.077 107.061,80.716 107.09,80.687 107.061,80.658 107.061,79.796 106.553,79.288 106.553,77.256 107.338,76.47 108.943,76.47 108.966,76.494 109.601,76.494 J12.3@110.949,75.146
"Pico LED B": D16.2 J12.4 U1.27 | length 17.7
  F.Cu w0.33: D16.2@105.75,83.488 105.75,82.735 104.775,81.76 104.775,79.034 104.753,79.012 101.76,79.012 104.775,79.012 104.775,76.367 105.996,75.146 J12.4@108.409,75.146
"PICO OUT BIT 0": J7.15 J11.15 U1.16 | length 103.3
  F.Cu w0.33: J11.15@128.808,57.211 130.133,55.886 133.639,55.886 134.938,57.185 J7.15@137.227,57.185
  In2.Cu w0.33: U1.16@83.34,73.827 88.2,73.827 v1(88.34,73.687)
  B.Cu w0.33: v1(88.34,73.687) 88.34,73.626 87.62,72.906 87.62,47.535 88.287,46.868 88.287,40.645 89.202,39.73 117.427,39.73 119.11,41.413 119.11,51.966 120.65,53.507 120.65,54.904 122.957,57.211 J11.15@128.808,57.211
"PICO OUT BIT 1": J7.13 J11.13 U1.7 | length 126.9
  F.Cu w0.33: J11.13@128.808,59.751 130.023,58.535 133.689,58.535 134.878,59.725 J7.13@137.227,59.725
  B.Cu w0.33: U1.7@83.34,96.687 85.34,94.687 85.34,81.692 94.84,72.192 94.84,64.781 89.348,59.288 89.348,41.179 89.736,40.791 116.988,40.791 118.049,41.852 118.049,51.966 117.907,52.109 117.907,54.307 123.35,59.751 J11.13@128.808,59.751
"PICO OUT BIT 2": J7.18 J11.18 U1.9 | length 125.8
  F.Cu w0.33: U1.9@83.34,91.607 88.42,91.607 89.154,90.873 89.154,90.187 89.154,76.367 v1(88.646,75.859) ; J11.18@131.348,54.671 133.724,54.671 135.023,55.97 138.442,55.97 J7.18@139.767,54.645
  B.Cu w0.33: v1(88.646,75.859) 88.012,75.859 86.941,74.788 86.941,47.464 87.757,46.649 87.757,40.426 88.983,39.2 117.646,39.2 119.64,41.194 119.64,50.592 122.174,53.126 122.174,54.904 123.156,55.886 130.133,55.886 J11.18@131.348,54.671
"Pico UART0 Rx": J12.6 U1.22 | length 10
  F.Cu w0.33: U1.22@101.12,66.207 101.225,66.312 102.187,66.312 108.409,72.533 J12.6@108.409,72.606
"Pico UART0 Tx": J12.7 U1.21 | length 13.2
  F.Cu w0.33: U1.21@101.76,63.772 104.118,63.772 106.426,66.08 106.426,68.493 106.784,68.85 109.718,68.85 J12.7@110.933,70.066
"POE SW PWR CM": PS2.34 R4.2 U1.32 | length 106.9
  F.Cu w0.25: PS2.34@60.635,36.682 59.854,35.901 59.854,29.88 64.085,25.649 R4.2@64.96,25.649
  F.Cu w0.33: PS2.34@60.635,36.682 PS2.34@61.344,35.972 ; v1(88.84,62.187) 90.34,63.687 90.34,89.387 92.56,91.607 U1.32@101.12,91.607
  In2.Cu w0.33: PS2.34@60.635,36.682 PS2.34@61.344,35.972 ; v1(84.34,57.687) v1(88.84,62.187)
  B.Cu w0.33: PS2.34@60.635,36.682 62.89,38.937 72.34,38.937 72.84,39.437 85.09,39.437 86.166,40.513 86.166,45.86 85.053,46.974 85.053,56.974 v1(84.34,57.687)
